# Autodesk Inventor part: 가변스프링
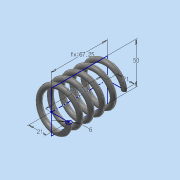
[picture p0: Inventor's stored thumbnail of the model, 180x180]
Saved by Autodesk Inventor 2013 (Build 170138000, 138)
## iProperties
Created: 2019-10
Part Number: 가변스프링
Material: 스테인리스강
Document SubType Name: Modeling
Designer: Administrator
Density: 8.08 g/cm^3
Mass: 147.816 g
Surface Area: 124.153 cm^2
Volume: 18.294 cm^3
Author: Administrator
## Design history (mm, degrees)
sketch "스케치1"
  geometry: L1 (0, 0)-(0, 67.25); L2 (0, 0)-(21, 0); L3 (0, 67.25)-(21, 67.25); C1 r 3 at (21, 0)
  constraints: 6 end point, 2 horizontal, 1 centre point, 1 coincident, 1 vertical
  dimensions: "d0" = 67.25 distance of L1.start L1.end (derived); "d1" = 21 distance of L1.start L2.end; "d3" = 21 distance of L1.end L3.end; "d4" = 6 diameter of C1
feature "코일1" sketch "스케치1" pitch "d5" = 10; turns "d7" = 5; dims "d6" = 67.25 (= d0), "d8" = 0, angle "d9" = 90 deg, angle "d10" = 90 deg, "d11" = 0, "d12" = 0
sketch "스케치2"
  geometry: L1 (67.25, 25)-(0, 25); L2 (0, 25)-(0, -25); L3 (0, -25)-(67.25, -25); L4 (67.25, -25)-(67.25, 25); 2 further points
  constraints: 8 end point, 2 parallel, 1 coincident, 1 horizontal, 1 midpoint, 1 perpendicular
  dimensions: "d14" = 67.25 distance of L1.start L1.end (= d0); "d16" = 50 distance of L3.end L1.start
extrude "돌출1" sketch "스케치2" stored distance "d17" = 0; taper "d18" = 0 deg
node "솔리드1"
